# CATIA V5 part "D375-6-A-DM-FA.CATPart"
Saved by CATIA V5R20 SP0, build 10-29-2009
Part number: D375-6-A-DM-FA
Bounding box of the stored display mesh (mm): x -8 to 0, y -3 to 3, z -3 to 3
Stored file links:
  C:\Users\Utente\Desktop\IO LAVORO\3D X SITO CF\X SITO\PLASTICA\D375\D375-6-A-DM-FA.CATPart
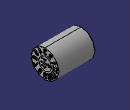
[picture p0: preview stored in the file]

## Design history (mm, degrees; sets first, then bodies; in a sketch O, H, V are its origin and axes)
Set1
  DatumSurface1 to DatumSurface216 "D375-6-A-DM-FA"
Body1 (main body)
